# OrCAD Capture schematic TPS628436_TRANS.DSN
size E; title: TPS628436 1.8-V to 5.5-V, 600-mA, 275-nA IQ,; rev: 1.0; note: Datasheet:SLVSFU8   EVM: SLUUCG5; note: Synchronous Step Down Converter
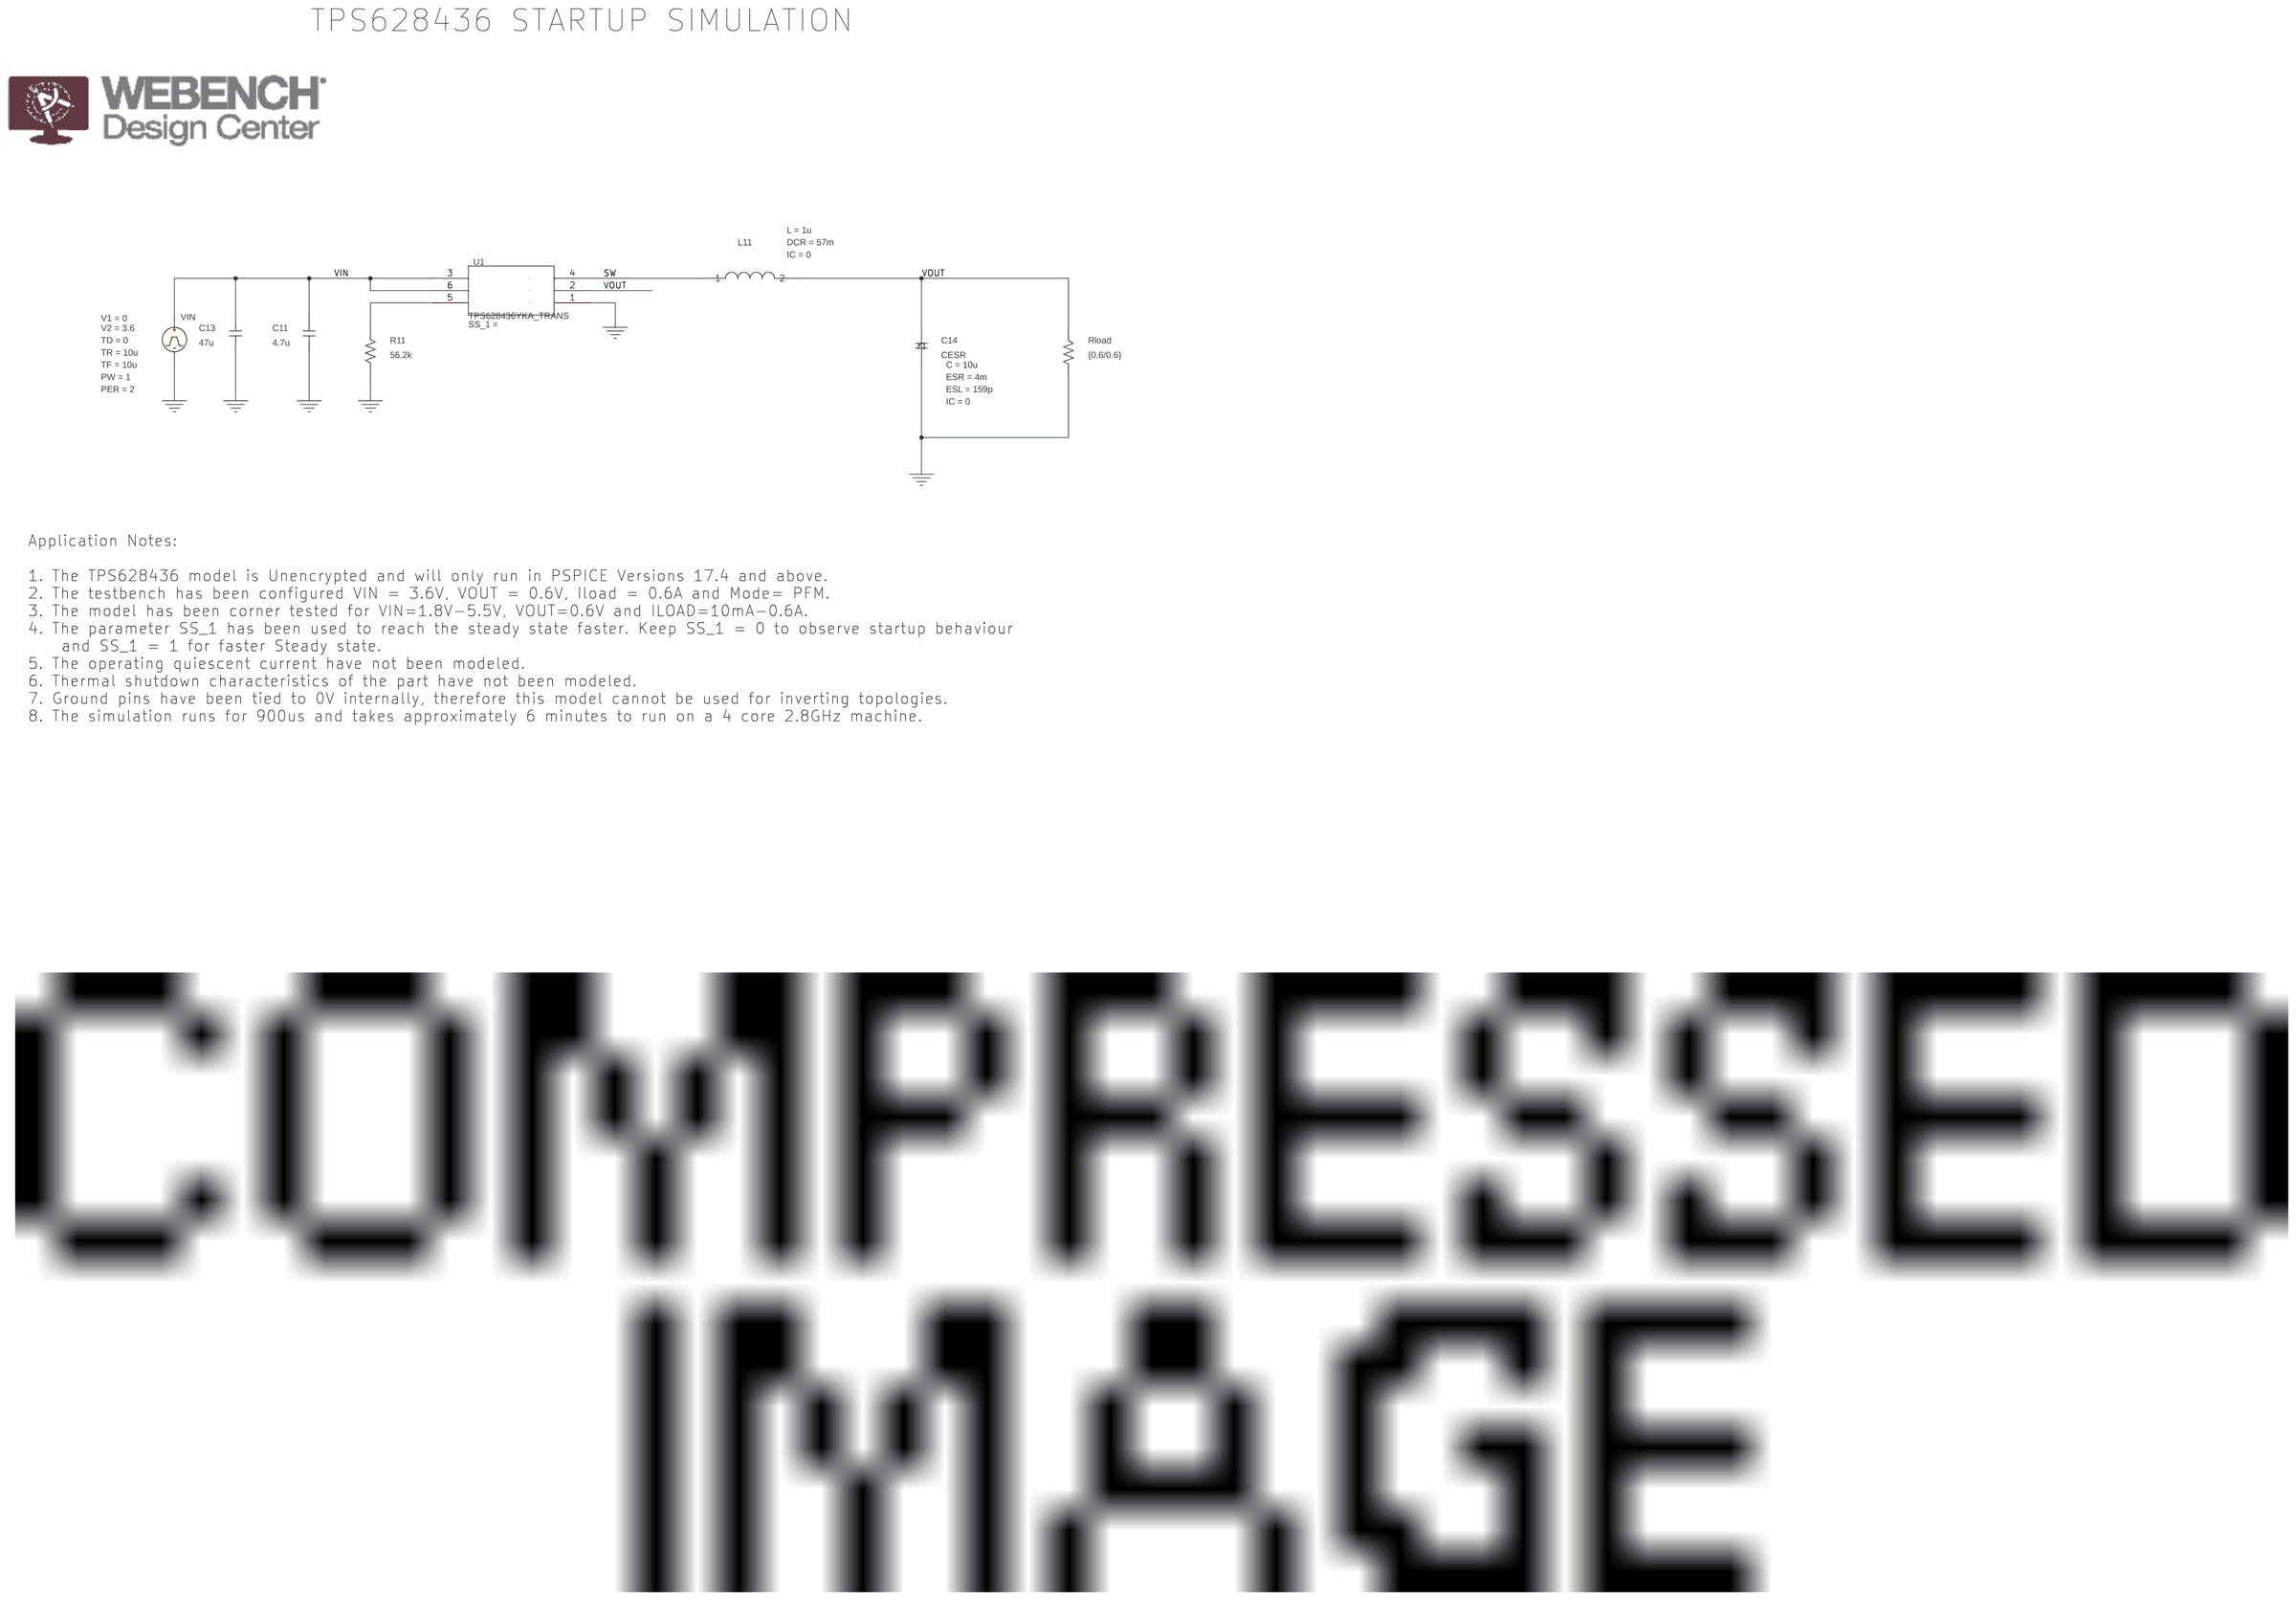
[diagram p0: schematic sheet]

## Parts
C11  4.7u  [RAD/CK05]
C13  47u  [RAD/CK05]
C14  CESR
L11  LDCR
R11  56.2k  [AX/RC05]
Rload  {0.6/0.6}  [AX/RC05]
U1  TPS628436YKA_TRANS  [YKA0006-IPC_A]
VIN  VPULSE

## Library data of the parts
C11 C13 = C
C14 = CESR: C: 10u; ESL: 159p; ESR: 4m; IC: 0; PSpiceTemplate: X^@REFDES %1 %2 @MODEL PARAMS: ?C|C=@C||C=10U| ?ESR|ESR=@ESR||ESR=2M| ?ESL|ESL=@ESL||ESL=1N| ?IC|IC=@IC||IC=0|
L11 = LDCR: DCR: 57m; IC: 0; L: 1u
R11 Rload = R
U1 = TPS628436YKA_TRANS
VIN = VPULSE: PER: 2; PW: 1; TD: 0; TF: 10u; TR: 10u; V1: 0; V2: 3.6

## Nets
VIN: C11.2 C13.2 U1.3(VIN) U1.6(EN) VIN.1(+)
0: C11.1 C13.1 C14.2 R11.1 Rload.2 U1.1(GND) VIN.2(-)
SW: L11.1 U1.4(SW)
VOUT: C14.1 L11.2 Rload.1 U1.2(VOS)
N16777421: R11.2 U1.5(VSET)

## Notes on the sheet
- TPS628436 STARTUP SIMULATION
- Application Notes:
  1. The TPS628436 model is Unencrypted and will only run in PSPICE Versions 17.4 and above.
  2. The testbench has been configured VIN = 3.6V, VOUT = 0.6V, Iload = 0.6A and Mode= PFM.
  3. The model has been corner tested for VIN=1.8V-5.5V, VOUT=0.6V and ILOAD=10mA-0.6A.
  4. The parameter SS_1 has been used to reach the steady state faster. Keep SS_1 = 0 to observe startup behaviour
      and SS_1 = 1 for faster Steady state.
  5. The operating quiescent current have not been modeled.
  6. Thermal shutdown characteristics of the part have not been modeled.
  7. Ground pins have been tied to 0V internally, therefore this model cannot be used for inverting topologies.
  8. The simulation runs for 900us and takes approximately 6 minutes to run on a 4 core 2.8GHz machine.
